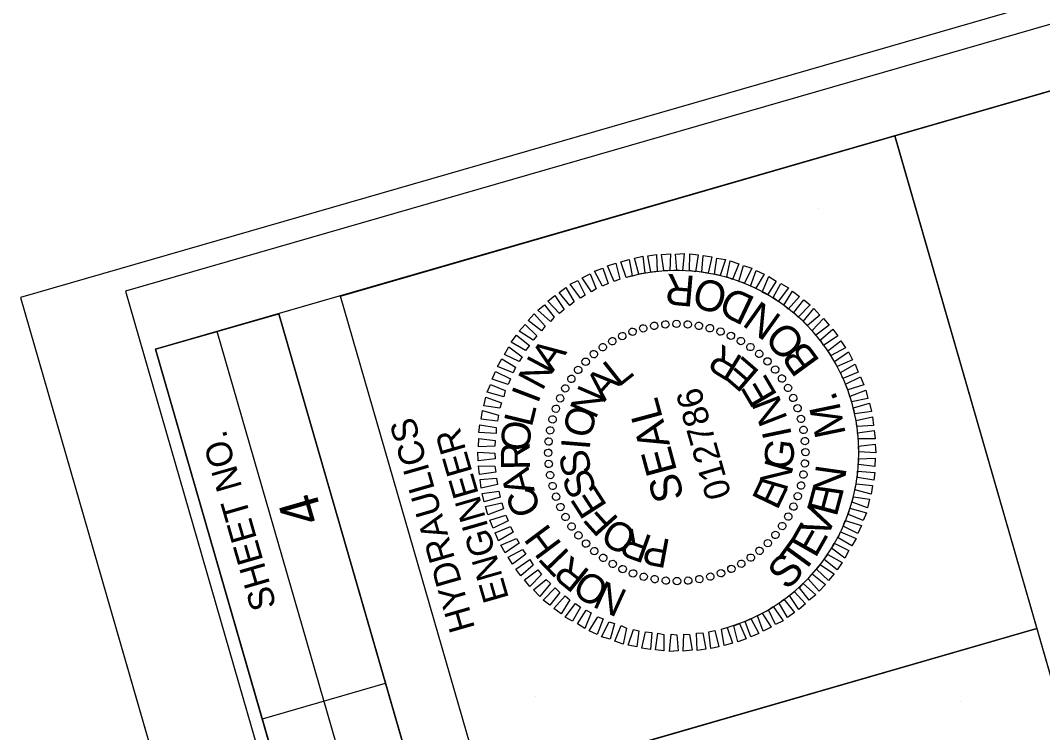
# Model space of a CAD drawing. Extents: x 2167139 to 2168658, y 842502 to 844423.
# Drawn here: x 2167138.9 to 2167338.2, y 844034.6 to 844173.5 of the extents above; entities that cross this region are included whole.
import ezdxf

# ---------------------------------------------------------------- set-up
doc = ezdxf.new("R2010")
doc.units = 0
for name, color, linetype in [('Old_Level_2', 7, 'Continuous'), ('Scratch_Level_0', 7, 'Continuous'), ('Sheet Cutting Line CELL', 7, 'Continuous'), ('Sheet Data Field CELL', 7, 'Continuous'), ('Sheet PE Seal CELL', 7, 'Continuous'), ('Sheet Plan CELL', 7, 'Continuous'), ('Sheet Plan Layout CELL', 7, 'Continuous'), ('Sheet Plot Border Inside CELL', 7, 'Continuous'), ('Sheet Plot Border Outside CELL', 7, 'Continuous')]:
    doc.layers.add(name, color=color, linetype=linetype)

msp = doc.modelspace()

# ---------------------------------------------------------------- linework, layer by layer
at = {"layer": 'Scratch_Level_0'}
msp.add_arc((2167266.92, 844089.2), 35.5, 286.1042, 106.1042, dxfattribs=at)
at = {"layer": 'Sheet Cutting Line CELL'}
msp.add_line((2167138.92, 844119.41), (2167605.9, 842501.98), dxfattribs=at)
at = {"layer": 'Sheet PE Seal CELL'}
for p, q in [((2167294.49, 844136.82), (2167294.49, 844136.82)), ((2167258.29, 844112.78), (2167258.29, 844112.78)), ((2167260.39, 844113.44), (2167260.39, 844113.44)), ((2167262.54, 844113.91), (2167262.54, 844113.91)), ((2167264.71, 844114.17), (2167264.71, 844114.17)), ((2167266.85, 844114.32), (2167266.85, 844114.32)), ((2167269.06, 844114.23), (2167269.06, 844114.23)), ((2167271.23, 844113.92), (2167271.23, 844113.92)), ((2167273.38, 844113.5), (2167273.38, 844113.5)), ((2167275.46, 844112.79), (2167275.46, 844112.79)), ((2167254.3, 844110.9), (2167254.3, 844110.9)), ((2167256.31, 844111.9), (2167256.31, 844111.9)), ((2167277.51, 844111.98), (2167277.51, 844111.98)), ((2167279.42, 844110.97), (2167279.42, 844110.97)), ((2167250.75, 844108.42), (2167250.75, 844108.42)), ((2167252.45, 844109.74), (2167252.45, 844109.74)), ((2167281.32, 844109.8), (2167281.32, 844109.8)), ((2167283, 844108.47), (2167283, 844108.47)), ((2167249.16, 844106.92), (2167249.16, 844106.92)), ((2167284.64, 844106.96), (2167284.64, 844106.96)), ((2167247.65, 844105.29), (2167247.65, 844105.29)), ((2167286.14, 844105.37), (2167286.14, 844105.37)), ((2167246.31, 844103.6), (2167246.31, 844103.6)), ((2167287.46, 844103.67), (2167287.46, 844103.67)), ((2167245.15, 844101.7), (2167245.15, 844101.7)), ((2167288.62, 844101.82), (2167288.62, 844101.82)), ((2167244.13, 844099.8), (2167244.13, 844099.8)), ((2167289.61, 844099.81), (2167289.61, 844099.81)), ((2167243.32, 844097.74), (2167243.32, 844097.74)), ((2167290.5, 844097.83), (2167290.5, 844097.83)), ((2167242.62, 844095.66), (2167242.62, 844095.66)), ((2167291.16, 844095.73), (2167291.16, 844095.73)), ((2167242.2, 844093.51), (2167242.2, 844093.51)), ((2167291.62, 844093.57), (2167291.62, 844093.57)), ((2167241.89, 844091.34), (2167241.89, 844091.34)), ((2167291.88, 844091.41), (2167291.88, 844091.41)), ((2167241.8, 844089.13), (2167241.8, 844089.13)), ((2167266.92, 844089.2), (2167266.92, 844089.2)), ((2167292.03, 844089.27), (2167292.03, 844089.27)), ((2167241.95, 844086.99), (2167241.95, 844086.99)), ((2167291.94, 844087.06), (2167291.94, 844087.06)), ((2167242.21, 844084.83), (2167242.21, 844084.83)), ((2167291.63, 844084.89), (2167291.63, 844084.89)), ((2167242.68, 844082.67), (2167242.68, 844082.67)), ((2167291.21, 844082.74), (2167291.21, 844082.74)), ((2167243.34, 844080.57), (2167243.34, 844080.57)), ((2167290.51, 844080.66), (2167290.51, 844080.66)), ((2167244.22, 844078.59), (2167244.22, 844078.59)), ((2167289.7, 844078.6), (2167289.7, 844078.6)), ((2167245.22, 844076.59), (2167245.22, 844076.59)), ((2167288.69, 844076.7), (2167288.69, 844076.7)), ((2167246.37, 844074.73), (2167246.37, 844074.73)), ((2167287.52, 844074.8), (2167287.52, 844074.8)), ((2167247.7, 844073.03), (2167247.7, 844073.03)), ((2167286.19, 844073.11), (2167286.19, 844073.11)), ((2167249.2, 844071.44), (2167249.2, 844071.44)), ((2167284.68, 844071.48), (2167284.68, 844071.48)), ((2167250.83, 844069.93), (2167250.83, 844069.93)), ((2167252.52, 844068.6), (2167252.52, 844068.6)), ((2167281.38, 844068.66), (2167281.38, 844068.66)), ((2167283.08, 844069.98), (2167283.08, 844069.98)), ((2167254.42, 844067.43), (2167254.42, 844067.43)), ((2167277.53, 844066.5), (2167277.53, 844066.5)), ((2167279.53, 844067.5), (2167279.53, 844067.5)), ((2167256.32, 844066.42), (2167256.32, 844066.42)), ((2167258.38, 844065.61), (2167258.38, 844065.61)), ((2167260.45, 844064.9), (2167260.45, 844064.9)), ((2167273.45, 844064.96), (2167273.45, 844064.96)), ((2167275.55, 844065.62), (2167275.55, 844065.62)), ((2167262.6, 844064.48), (2167262.6, 844064.48)), ((2167264.78, 844064.17), (2167264.78, 844064.17)), ((2167266.99, 844064.08), (2167266.99, 844064.08)), ((2167269.13, 844064.23), (2167269.13, 844064.23)), ((2167271.29, 844064.49), (2167271.29, 844064.49)), ((2167239.34, 844041.58), (2167239.34, 844041.58)), ((2167322.24, 844040.69), (2167322.24, 844040.69))]:
    msp.add_line(p, q, dxfattribs=at)
for points in [[(2167257.07, 844123.31), (2167256.02, 844126.39), (2167257.66, 844126.86), (2167258.22, 844123.64)], [(2167259.49, 844123.95), (2167258.68, 844127.1), (2167260.29, 844127.46), (2167260.67, 844124.19)], [(2167261.86, 844124.38), (2167261.26, 844127.54), (2167262.95, 844127.82), (2167263.08, 844124.47)], [(2167264.42, 844124.7), (2167263.95, 844127.79), (2167265.68, 844127.93), (2167265.54, 844124.61)], [(2167266.91, 844124.74), (2167266.67, 844127.9), (2167268.36, 844128.02), (2167268.03, 844124.65)], [(2167269.42, 844124.69), (2167269.43, 844127.92), (2167271.1, 844127.72), (2167270.58, 844124.45)], [(2167271.81, 844124.34), (2167272.06, 844127.63), (2167273.76, 844127.34), (2167273.01, 844124.16)], [(2167274.3, 844124.01), (2167274.71, 844127.1), (2167276.41, 844126.81), (2167275.38, 844123.7)], [(2167276.7, 844123.46), (2167277.36, 844126.56), (2167278.99, 844125.99), (2167277.79, 844122.94)], [(2167252.46, 844121.61), (2167250.89, 844124.54), (2167252.48, 844125.16), (2167253.56, 844122.14)], [(2167254.68, 844122.57), (2167253.4, 844125.58), (2167255, 844126.14), (2167255.81, 844122.99)], [(2167279.04, 844122.57), (2167279.92, 844125.64), (2167281.58, 844125.13), (2167280.13, 844122.21)], [(2167281.28, 844121.66), (2167282.43, 844124.7), (2167283.98, 844124), (2167282.34, 844121.23)], [(2167248.14, 844119.27), (2167246.15, 844122.03), (2167247.65, 844122.77), (2167249.05, 844119.9)], [(2167250.28, 844120.51), (2167248.49, 844123.28), (2167250.04, 844124.04), (2167251.2, 844121.09)], [(2167283.59, 844120.5), (2167284.85, 844123.52), (2167286.3, 844122.64), (2167284.58, 844119.96)], [(2167246.06, 844117.84), (2167243.96, 844120.41), (2167245.3, 844121.37), (2167246.93, 844118.61)], [(2167285.73, 844119.4), (2167287.23, 844122.13), (2167288.72, 844121.31), (2167286.66, 844118.68)], [(2167287.77, 844117.91), (2167289.48, 844120.64), (2167290.86, 844119.64), (2167288.66, 844117.18)], [(2167244.05, 844116.32), (2167241.79, 844118.74), (2167243.14, 844119.81), (2167244.97, 844117.11)], [(2167289.74, 844116.5), (2167291.68, 844118.99), (2167292.95, 844118), (2167290.62, 844115.61)], [(2167242.26, 844114.76), (2167239.8, 844116.97), (2167241.11, 844118.02), (2167243.01, 844115.6)], [(2167291.55, 844114.74), (2167293.63, 844117.26), (2167294.83, 844115.99), (2167292.39, 844113.99)], [(2167240.51, 844112.9), (2167237.95, 844114.92), (2167239.12, 844116.25), (2167241.27, 844113.85)], [(2167293.3, 844113), (2167295.55, 844115.32), (2167296.65, 844114.02), (2167294.04, 844112.07)], [(2167238.9, 844111.09), (2167236.2, 844112.86), (2167237.33, 844114.17), (2167239.64, 844111.93)], [(2167294.92, 844111.18), (2167297.35, 844113.23), (2167298.34, 844111.96), (2167295.55, 844110.06)], [(2167237.44, 844109.1), (2167234.64, 844110.69), (2167235.65, 844112.07), (2167238.21, 844110.05)], [(2167296.37, 844109.05), (2167298.93, 844110.99), (2167299.79, 844109.62), (2167297, 844108.14)], [(2167236.2, 844106.92), (2167233.34, 844108.34), (2167234.16, 844109.82), (2167236.76, 844107.87)], [(2167297.66, 844106.92), (2167300.39, 844108.81), (2167301.2, 844107.27), (2167298.19, 844105.98)], [(2167235.01, 844104.71), (2167231.95, 844105.96), (2167232.77, 844107.44), (2167235.47, 844105.83)], [(2167298.85, 844104.77), (2167301.7, 844106.43), (2167302.31, 844104.88), (2167299.33, 844103.66)], [(2167234.05, 844102.45), (2167230.9, 844103.47), (2167231.59, 844105.02), (2167234.46, 844103.56)], [(2167233.18, 844100.07), (2167229.91, 844100.94), (2167230.56, 844102.49), (2167233.45, 844101.29)], [(2167299.81, 844102.55), (2167302.73, 844103.96), (2167303.39, 844102.38), (2167300.28, 844101.44)], [(2167300.74, 844100.21), (2167303.79, 844101.36), (2167304.2, 844099.76), (2167301.02, 844099.05)], [(2167232.42, 844097.82), (2167229.31, 844098.33), (2167229.71, 844100), (2167232.74, 844098.9)], [(2167301.36, 844097.89), (2167304.48, 844098.8), (2167304.89, 844097.2), (2167301.64, 844096.73)], [(2167231.96, 844095.29), (2167228.78, 844095.67), (2167229.02, 844097.36), (2167232.18, 844096.5)], [(2167231.67, 844092.87), (2167228.32, 844093.1), (2167228.51, 844094.61), (2167231.68, 844094.07)], [(2167301.91, 844095.45), (2167305.08, 844096.16), (2167305.25, 844094.49), (2167302.05, 844094.24)], [(2167302.19, 844093.03), (2167305.39, 844093.49), (2167305.6, 844091.83), (2167302.38, 844091.84)], [(2167231.43, 844090.45), (2167228.24, 844090.32), (2167228.29, 844091.94), (2167231.47, 844091.56)], [(2167302.37, 844090.43), (2167305.63, 844090.85), (2167305.72, 844089.11), (2167302.42, 844089.35)], [(2167231.47, 844087.97), (2167228.21, 844087.55), (2167228.12, 844089.29), (2167231.42, 844089.05)], [(2167231.65, 844085.37), (2167228.45, 844084.91), (2167228.23, 844086.57), (2167231.46, 844086.56)], [(2167302.41, 844087.95), (2167305.59, 844088.08), (2167305.54, 844086.46), (2167302.36, 844086.84)], [(2167302.17, 844085.53), (2167305.51, 844085.3), (2167305.33, 844083.79), (2167302.15, 844084.33)], [(2167231.93, 844082.95), (2167228.75, 844082.24), (2167228.58, 844083.91), (2167231.79, 844084.16)], [(2167301.88, 844083.11), (2167305.06, 844082.73), (2167304.82, 844081.04), (2167301.66, 844081.9)], [(2167232.48, 844080.51), (2167229.36, 844079.6), (2167228.95, 844081.2), (2167232.19, 844081.67)], [(2167301.41, 844080.58), (2167304.52, 844080.07), (2167304.12, 844078.4), (2167301.1, 844079.5)], [(2167233.1, 844078.19), (2167230.04, 844077.04), (2167229.63, 844078.64), (2167232.81, 844079.35)], [(2167234.03, 844075.85), (2167231.11, 844074.44), (2167230.44, 844076.02), (2167233.55, 844076.96)], [(2167300.66, 844078.33), (2167303.93, 844077.46), (2167303.28, 844075.92), (2167300.38, 844077.11)], [(2167234.98, 844073.63), (2167232.13, 844071.97), (2167231.53, 844073.52), (2167234.51, 844074.74)], [(2167299.78, 844075.95), (2167302.94, 844074.93), (2167302.24, 844073.38), (2167299.37, 844074.84)], [(2167298.82, 844073.69), (2167301.89, 844072.44), (2167301.07, 844070.96), (2167298.36, 844072.57)], [(2167236.18, 844071.48), (2167233.44, 844069.6), (2167232.63, 844071.13), (2167235.65, 844072.42)], [(2167297.64, 844071.48), (2167300.49, 844070.06), (2167299.67, 844068.58), (2167297.08, 844070.53)], [(2167237.47, 844069.35), (2167234.9, 844067.42), (2167234.04, 844068.78), (2167236.84, 844070.26)], [(2167296.4, 844069.3), (2167299.2, 844067.71), (2167298.19, 844066.33), (2167295.63, 844068.35)], [(2167238.92, 844067.22), (2167236.49, 844065.17), (2167235.5, 844066.44), (2167238.28, 844068.34)], [(2167294.94, 844067.31), (2167297.64, 844065.54), (2167296.51, 844064.23), (2167294.19, 844066.47)], [(2167240.53, 844065.4), (2167238.29, 844063.08), (2167237.19, 844064.38), (2167239.8, 844066.33)], [(2167293.33, 844065.5), (2167295.89, 844063.48), (2167294.71, 844062.15), (2167292.56, 844064.55)], [(2167242.28, 844063.67), (2167240.2, 844061.14), (2167239, 844062.41), (2167241.44, 844064.41)], [(2167244.1, 844061.9), (2167242.16, 844059.41), (2167240.89, 844060.4), (2167243.21, 844062.79)], [(2167291.58, 844063.64), (2167294.03, 844061.43), (2167292.73, 844060.38), (2167290.83, 844062.8)], [(2167246.06, 844060.49), (2167244.35, 844057.76), (2167242.97, 844058.76), (2167245.18, 844061.22)], [(2167287.78, 844060.56), (2167289.87, 844057.99), (2167288.54, 844057.04), (2167286.91, 844059.79)], [(2167289.79, 844062.08), (2167292.05, 844059.66), (2167290.69, 844058.59), (2167288.87, 844061.29)], [(2167248.11, 844059), (2167246.6, 844056.27), (2167245.12, 844057.09), (2167247.17, 844059.72)], [(2167285.7, 844059.13), (2167287.69, 844056.37), (2167286.19, 844055.63), (2167284.78, 844058.5)], [(2167250.25, 844057.9), (2167248.98, 844054.88), (2167247.53, 844055.76), (2167249.26, 844058.44)], [(2167252.56, 844056.74), (2167251.4, 844053.7), (2167249.85, 844054.4), (2167251.5, 844057.17)], [(2167281.38, 844056.79), (2167282.95, 844053.86), (2167281.36, 844053.24), (2167280.28, 844056.26)], [(2167283.56, 844057.89), (2167285.34, 844055.12), (2167283.79, 844054.36), (2167282.63, 844057.31)], [(2167254.8, 844055.83), (2167253.91, 844052.76), (2167252.26, 844053.27), (2167253.71, 844056.19)], [(2167257.14, 844054.94), (2167256.47, 844051.84), (2167254.85, 844052.41), (2167256.05, 844055.46)], [(2167259.53, 844054.39), (2167259.12, 844051.3), (2167257.43, 844051.59), (2167258.46, 844054.7)], [(2167276.76, 844055.09), (2167277.81, 844052.01), (2167276.18, 844051.54), (2167275.61, 844054.76)], [(2167279.15, 844055.83), (2167280.44, 844052.82), (2167278.83, 844052.26), (2167278.03, 844055.41)], [(2167262.02, 844054.06), (2167261.78, 844050.77), (2167260.08, 844051.06), (2167260.83, 844054.24)], [(2167264.41, 844053.71), (2167264.41, 844050.48), (2167262.74, 844050.68), (2167263.25, 844053.95)], [(2167266.93, 844053.66), (2167267.16, 844050.5), (2167265.48, 844050.38), (2167265.81, 844053.75)], [(2167269.41, 844053.7), (2167269.89, 844050.61), (2167268.16, 844050.47), (2167268.29, 844053.79)], [(2167271.97, 844054.02), (2167272.57, 844050.86), (2167270.88, 844050.59), (2167270.75, 844053.93)], [(2167274.35, 844054.45), (2167275.15, 844051.3), (2167273.54, 844050.94), (2167273.17, 844054.21)]]:
    msp.add_lwpolyline(points, close=True, dxfattribs=at)
for centre, major_axis in [((2167262.52, 844113.89), (-0.126, 0.709)), ((2167264.69, 844114.18), (-0.064, 0.717)), ((2167266.87, 844114.28), (-0.001, 0.72)), ((2167269.06, 844114.19), (0.061, 0.717)), ((2167271.23, 844113.91), (0.124, 0.709)), ((2167256.28, 844111.91), (-0.305, 0.652)), ((2167258.3, 844112.75), (-0.247, 0.676)), ((2167260.38, 844113.41), (-0.188, 0.695)), ((2167273.36, 844113.44), (0.185, 0.696)), ((2167275.45, 844112.78), (0.245, 0.677)), ((2167277.48, 844111.95), (0.303, 0.653)), ((2167252.5, 844109.72), (-0.414, 0.589)), ((2167254.34, 844110.9), (-0.361, 0.623)), ((2167279.42, 844110.94), (0.359, 0.624)), ((2167281.27, 844109.77), (0.412, 0.591)), ((2167250.76, 844108.38), (-0.464, 0.551)), ((2167283, 844108.44), (0.462, 0.552)), ((2167249.15, 844106.9), (-0.51, 0.508)), ((2167284.62, 844106.97), (0.508, 0.51)), ((2167247.68, 844105.29), (-0.552, 0.462)), ((2167286.1, 844105.36), (0.551, 0.464)), ((2167287.44, 844103.62), (0.589, 0.414)), ((2167245.17, 844101.7), (-0.624, 0.359)), ((2167246.35, 844103.55), (-0.591, 0.412)), ((2167288.61, 844101.78), (0.623, 0.361)), ((2167244.17, 844099.76), (-0.653, 0.303)), ((2167289.63, 844099.84), (0.652, 0.305)), ((2167243.33, 844097.74), (-0.677, 0.245)), ((2167290.47, 844097.82), (0.676, 0.247)), ((2167242.68, 844095.65), (-0.696, 0.185)), ((2167291.13, 844095.74), (0.695, 0.188)), ((2167242.21, 844093.51), (-0.709, 0.124)), ((2167291.61, 844093.6), (0.709, 0.126)), ((2167241.93, 844091.34), (-0.717, 0.061)), ((2167291.9, 844091.43), (0.717, 0.064)), ((2167241.84, 844089.15), (-0.72, -0.001)), ((2167292, 844089.25), (0.72, 0.001)), ((2167241.94, 844086.97), (-0.717, -0.064)), ((2167291.91, 844087.06), (0.717, -0.061)), ((2167242.23, 844084.8), (-0.709, -0.126)), ((2167291.62, 844084.89), (0.709, -0.124)), ((2167242.7, 844082.66), (-0.695, -0.188)), ((2167291.15, 844082.75), (0.696, -0.185)), ((2167243.37, 844080.58), (-0.676, -0.247)), ((2167290.5, 844080.67), (0.677, -0.245)), ((2167244.21, 844078.56), (-0.652, -0.305)), ((2167289.67, 844078.64), (0.653, -0.303)), ((2167245.22, 844076.62), (-0.623, -0.361)), ((2167288.66, 844076.7), (0.624, -0.359)), ((2167246.4, 844074.78), (-0.589, -0.414)), ((2167287.49, 844074.85), (0.591, -0.412)), ((2167247.73, 844073.04), (-0.551, -0.464)), ((2167286.16, 844073.11), (0.552, -0.462)), ((2167249.22, 844071.43), (-0.508, -0.51)), ((2167250.83, 844069.96), (-0.462, -0.552)), ((2167283.07, 844070.02), (0.464, -0.551)), ((2167284.68, 844071.5), (0.51, -0.508)), ((2167252.57, 844068.63), (-0.412, -0.591)), ((2167281.34, 844068.68), (0.414, -0.589)), ((2167254.42, 844067.46), (-0.359, -0.624)), ((2167256.36, 844066.45), (-0.303, -0.653)), ((2167277.56, 844066.49), (0.305, -0.652)), ((2167279.5, 844067.5), (0.361, -0.623)), ((2167258.38, 844065.62), (-0.245, -0.677)), ((2167260.47, 844064.96), (-0.185, -0.696)), ((2167262.61, 844064.49), (-0.124, -0.709)), ((2167264.78, 844064.21), (-0.061, -0.717)), ((2167266.96, 844064.12), (0.001, -0.72)), ((2167269.15, 844064.22), (0.064, -0.717)), ((2167271.32, 844064.51), (0.126, -0.709)), ((2167273.45, 844064.99), (0.188, -0.695)), ((2167275.54, 844065.65), (0.247, -0.676))]:
    msp.add_ellipse(centre, major_axis=major_axis, ratio=0.999708, dxfattribs=at)
at = {"layer": 'Sheet Plan CELL'}
for p, q in [((2167244.82, 843924.07), (2167189.31, 844116.25)), ((2167244.82, 843924.07), (2167189.31, 844116.25)), ((2167232.78, 843920.58), (2167177.3, 844112.79)), ((2167229.07, 844023.66), (2167337.11, 844054.87)), ((2167186.11, 844037.24), (2167210.12, 844044.22))]:
    msp.add_line(p, q, dxfattribs=at)
for points in [[(2167165.23, 844109.34), (2167581.32, 842668.17), (2168590.12, 842959.42), (2168174.04, 844400.57)], [(2168590.12, 842959.42), (2167581.35, 842668.15), (2167220.72, 843917.11), (2167364.89, 843958.75), (2167309.41, 844150.94), (2168174.04, 844400.57)], [(2167229.07, 844023.66), (2167201.32, 844119.72), (2167309.41, 844150.94), (2167337.16, 844054.87)], [(2167220.72, 843917.11), (2167165.23, 844109.34), (2167189.31, 844116.25), (2167244.82, 843924.07)], [(2167256.82, 843927.54), (2167229.07, 844023.66), (2167337.16, 844054.87), (2167364.89, 843958.75)]]:
    msp.add_lwpolyline(points, close=True, dxfattribs=at)
at = {"layer": 'Sheet Plan Layout CELL'}
msp.add_lwpolyline([(2167434.8, 843938.11), (2167368.43, 844167.99), (2167165.23, 844109.35), (2167231.61, 843879.44)], close=True, dxfattribs=at)
at = {"layer": 'Sheet Plot Border Inside CELL'}
msp.add_lwpolyline([(2168635.11, 842812.65), (2168172.98, 844413.26), (2167159.38, 844120.64), (2167621.51, 842520.01)], close=True, dxfattribs=at)
at = {"layer": 'Sheet Plot Border Outside CELL'}
msp.add_lwpolyline([(2168657.93, 842805.71), (2168190.95, 844423.15), (2167138.92, 844119.41), (2167605.9, 842501.98)], close=True, dxfattribs=at)

# ---------------------------------------------------------------- texts
at = {"layer": 'Old_Level_2'}
for s, rotation, p in [('R', 175.0109, (2167270.65, 844123.59)), ('O', 164.0253, (2167277.22, 844121.79)), ('D', 154.6406, (2167282.48, 844119.29)), ('N', 144.4481, (2167287.64, 844115.63)), ('O', 133.4626, (2167292.38, 844110.74)), ('B', 126.1487, (2167294.98, 844107.02)), ('.', 112.6223, (2167298.46, 844099.4)), ('M', 101.6662, (2167299.91, 844092.76)), ('N', 81.7805, (2167299.25, 844080.48)), ('E', 75.0247, (2167298.06, 844076.46)), ('V', 67.1821, (2167296.1, 844072.01)), ('E', 60.4263, (2167293.94, 844068.41)), ('T', 53.9642, (2167291.49, 844065.23)), ('S', 47.0027, (2167288.47, 844062.14))]:
    msp.add_text(s, height=6, rotation=rotation, dxfattribs=at).set_placement(p)
at = {"layer": 'Sheet Data Field CELL'}
msp.add_text('4', height=7.75, rotation=106.1042, dxfattribs=at).set_placement((2167198.08, 844076.18))
at = {"layer": 'Sheet PE Seal CELL'}
for s, height, rotation, p in [('A', 5.64, 54.7214, (2167242.72, 844104.7)), ('R', 5.64, 148.5856, (2167280.06, 844107.67)), ('N', 5.64, 61.9231, (2167240.7, 844101.04)), ('L', 5.64, 38.5051, (2167255.53, 844101.79)), ('E', 5.64, 139.2283, (2167283.3, 844104.91)), ('A', 5.64, 47.8645, (2167252.76, 844098.95)), ('E', 5.64, 120.516, (2167286.65, 844100.36)), ('I', 5.64, 69.1243, (2167239.81, 844098.55)), ('N', 5.64, 66.5808, (2167251.05, 844095.5)), ('012786', 4.975, 106.1042, (2167277.6, 844080.88)), ('SEAL', 5.998, 105.1042, (2167268.41, 844080.42)), ('N', 5.64, 111.1606, (2167288.6, 844095.77)), ('L', 5.64, 76.3251, (2167238.63, 844093.99)), ('O', 5.64, 75.9377, (2167250.06, 844091.72)), ('O', 5.64, 83.5254, (2167238.07, 844089.25)), ('I', 5.64, 101.8054, (2167289.38, 844092.51)), ('R', 5.64, 90.7253, (2167238.28, 844085.82)), ('I', 5.64, 85.2938, (2167249.94, 844089.61)), ('G', 5.64, 83.0944, (2167289.37, 844085.69)), ('S', 5.64, 104.0046, (2167250.46, 844085.28)), ('A', 5.64, 105.1245, (2167239.25, 844081.73)), ('N', 5.64, 73.7382, (2167288.26, 844081.42)), ('S', 5.64, 113.3598, (2167251.51, 844081.84)), ('E', 5.64, 122.7153, (2167253.47, 844078.81)), ('E', 5.64, 64.3811, (2167286.5, 844077.78)), ('C', 5.64, 112.3241, (2167240.64, 844078.02)), ('F', 5.64, 132.0712, (2167255.8, 844076.15)), ('H', 5.64, 126.7237, (2167244.67, 844071.27)), ('O', 5.64, 150.7854, (2167259.55, 844073.8)), ('R', 5.64, 160.1439, (2167262.39, 844072.8)), ('T', 5.64, 133.924, (2167247.15, 844068.61)), ('P', 5.64, 169.5031, (2167265.91, 844072.15)), ('R', 5.64, 141.1247, (2167250.21, 844065.95)), ('O', 5.64, 148.3259, (2167254.15, 844063.5)), ('N', 5.64, 155.5277, (2167257.57, 844062.09))]:
    msp.add_text(s, height=height, rotation=rotation, dxfattribs=at).set_placement(p)
at = {"layer": 'Sheet Plan CELL'}
for s, p in [('HYDRAULICS', (2167227.61, 844054.95)), ('SHEET NO.', (2167188.89, 844059.22)), ('ENGINEER', (2167234.21, 844060.77))]:
    msp.add_text(s, height=5, rotation=106.1042, dxfattribs=at).set_placement(p)

doc.saveas('drawing.dxf')
